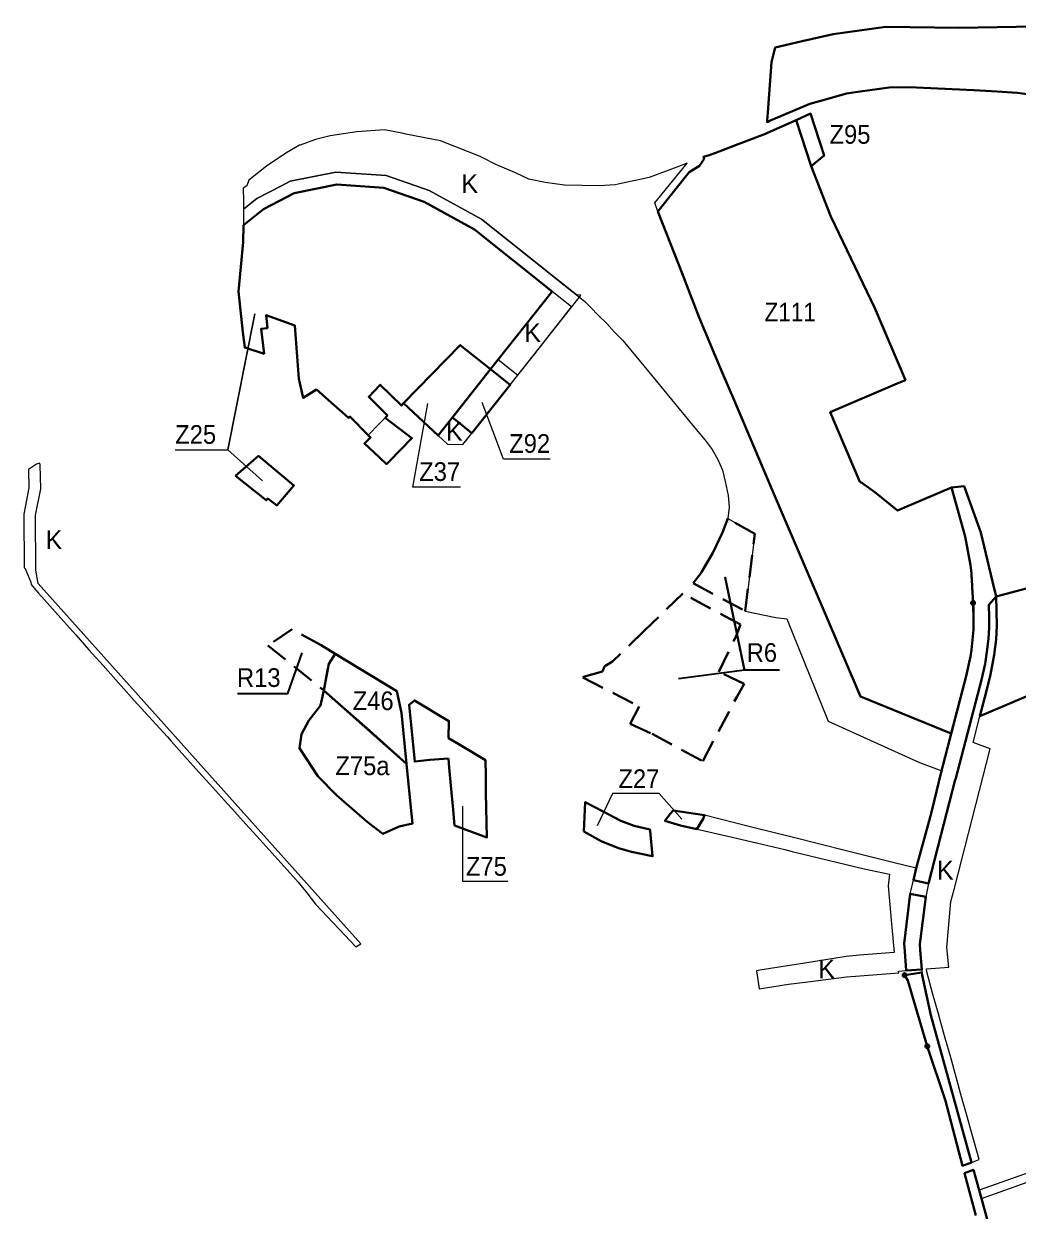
# Model space of a CAD drawing. Extents: x -650276 to -642489, y -1074311 to -1066658.
# Drawn here: x -650276 to -649001, y -1070690 to -1069167 of the extents above; entities that cross this region are included whole.
import ezdxf

# ---------------------------------------------------------------- set-up
doc = ezdxf.new("R2010")
doc.units = 0
doc.header["$LTSCALE"] = 9.6
doc.header["$PDMODE"] = 32
doc.header["$PDSIZE"] = 4.8
doc.linetypes.add('MEDIUM_DASHED', pattern=[4.5, 3, -1.5])
for name, color, linetype, lineweight in [('42', 7, 'Continuous', 25), ('44', 7, 'Continuous', 40), ('45', 7, 'Continuous', 40), ('46', 7, 'Continuous', 13), ('47', 7, 'Continuous', 13), ('48', 7, 'Continuous', 13), ('61', 7, 'MEDIUM_DASHED', 40), ('62', 7, 'Continuous', 35)]:
    doc.layers.add(name, color=color, linetype=linetype, lineweight=lineweight)

msp = doc.modelspace()

# ---------------------------------------------------------------- linework, layer by layer
at = {"layer": '42'}
msp.add_lwpolyline([(-649641.978, -1069618.226), (-649572.972, -1069530.758), (-649561.91, -1069516.78), (-649561.17, -1069515.83), (-649566.951, -1069515.099), (-649688.625, -1069418.156), (-649755.971, -1069381.179), (-649810.846, -1069362.154), (-649875.434, -1069357.751), (-649934.363, -1069369.537), (-649945.397, -1069375.277), (-649977.239, -1069391.714), (-649994.329, -1069405.451), (-649994.293, -1069425.949), (-649994.53, -1069447.61), (-650000.59, -1069511.15), (-649992.59, -1069582.88), (-649967.81, -1069590.74), (-649971.38, -1069558.79), (-649963.43, -1069557.91), (-649965.26, -1069541.51), (-649928.48, -1069554.57), (-649924.62, -1069608.53), (-649923.17, -1069623.14), (-649918.35, -1069643.45), (-649917.38, -1069647.56), (-649900.64, -1069636.78), (-649877.82, -1069656.83), (-649859.96, -1069672.53), (-649859.17, -1069673.22), (-649857.49, -1069671.46), (-649833.94, -1069695.24), (-649833.94, -1069695.24), (-649819.98, -1069680.92), (-649809.47, -1069670.13), (-649833.38, -1069646.08), (-649818.71, -1069630.64), (-649791.3, -1069657.21), (-649788.91, -1069654.4), (-649744.517, -1069695.746), (-649744.517, -1069695.746), (-649732.52, -1069706.92), (-649712.64, -1069707.43), (-649708.322, -1069702.293), (-649701.211, -1069692.826), (-649651.773, -1069630.879), (-649651.846, -1069630.821), (-649651.846, -1069630.82)], close=True, dxfattribs=at)
at = {"layer": '44'}
for p, q in [((-649058.858, -1069889.759), (-649057.868, -1069910.51)), ((-649057.134, -1069932.873), (-649057.868, -1069910.51)), ((-649146.163, -1070347.543), (-649145.424, -1070357.637))]:
    msp.add_line(p, q, dxfattribs=at)
for points in [[(-648781.015, -1069167.44), (-649076.02, -1069172.683), (-649169.781, -1069171.432), (-649237.512, -1069180.731), (-649277.021, -1069189.913), (-649306.455, -1069196.754), (-649311.633, -1069197.958), (-649316.47, -1069216.91), (-649321.32, -1069281.47), (-649322.09, -1069291.73), (-649322.22, -1069293.54), (-649319.72, -1069292.47), (-649267.5, -1069270.41), (-649242.5, -1069263.3), (-649220.18, -1069257.03), (-649202.63, -1069254.4), (-649165.62, -1069249.43), (-649139.63, -1069248.73), (-649056.95, -1069252.55), (-649026.955, -1069254.366), (-649001.3, -1069255.92), (-648968.49, -1069260.36)], [(-649061.138, -1069979.243), (-649061.138, -1069979.243), (-649061.139, -1069979.254), (-649066.487, -1070004.267), (-649098.65, -1070127.795), (-649110.925, -1070177.113), (-649114.174, -1070189.816), (-649130.712, -1070250.935), (-649134.294, -1070266.095), (-649115.159, -1070270.568), (-649095.152, -1070193.731), (-649093.095, -1070186.132), (-649095.152, -1070193.731), (-649080.924, -1070137.409), (-649080.38, -1070136.996), (-649047.131, -1070009.304), (-649042.468, -1069988.477), (-649042.468, -1069988.477), (-649039.966, -1069973.035), (-649037.98, -1069956.626), (-649037.322, -1069942.129), (-649037.137, -1069928.996), (-649037.665, -1069912.977), (-649028.017, -1069902.109), (-649032.928, -1069882.782), (-649048, -1069820), (-649069.4, -1069760.67), (-649085.41, -1069762.44), (-649068, -1069825.147), (-649060.897, -1069861.994)], [(-649138.43, -1070283.6), (-649146.163, -1070347.543), (-649146.163, -1070347.543)], [(-649125.503, -1070355.837), (-649126.069, -1070348.097), (-649118.257, -1070287.455), (-649138.43, -1070283.6)], [(-649145.424, -1070357.637), (-649143.633, -1070382.123), (-649123.693, -1070380.572), (-649125.503, -1070355.837)], [(-649059.951, -1070628.223), (-649112.14, -1070439.152), (-649123.138, -1070388.16), (-649123.385, -1070384.775), (-649145.73, -1070387.91)], [(-649145.73, -1070387.91), (-649141.48, -1070394.84), (-649132.07, -1070426.81), (-649116.56, -1070479.19)], [(-649116.56, -1070479.19), (-649093.2, -1070549.1), (-649071.33, -1070632.6), (-649059.951, -1070628.223)], [(-649025.129, -1070754.377), (-649047.11, -1070674.743), (-649050.081, -1070663.981), (-649057.338, -1070637.689), (-649068.65, -1070642.23), (-649068.65, -1070642.23), (-649054.31, -1070696.44)]]:
    msp.add_lwpolyline(points, dxfattribs=at)
msp.add_lwpolyline([(-649701.211, -1069692.826), (-649651.773, -1069630.879), (-649677.124, -1069610.681), (-649726.033, -1069672.415)], close=True, dxfattribs=at)
at = {"layer": '44', "lineweight": 13}
msp.add_lwpolyline([(-649600.782, -1069725.864), (-649660.57, -1069725.864), (-649688.04, -1069653.176)], dxfattribs=at)
at = {"layer": '44'}
for centre, radius, start, end in [((-649633.43, -1069918.001), 575.266, 2.81398, 5.58706), ((-649347.129, -1069931.193), 290, 350.46253, 4.08974), ((-649347.129, -1069931.193), 290, 359.66809, 4.08974)]:
    msp.add_arc(centre, radius, start, end, dxfattribs=at)
for p in [(-649145.73, -1070387.91), (-649116.56, -1070479.19)]:
    msp.add_point(p, dxfattribs=at)
at = {"layer": '45'}
msp.add_line((-649057.868, -1069910.51), (-649058.82, -1069890.548), dxfattribs=at)
for points in [[(-649060.897, -1069861.994), (-649068, -1069825.147), (-649085.41, -1069762.44), (-649085.41, -1069762.44), (-649099.75, -1069768.575), (-649154.76, -1069792.11), (-649184.05, -1069768.45), (-649200.64, -1069756.53), (-649202.99, -1069754.99), (-649241.11, -1069665.9), (-649155.082, -1069629.097), (-649144.57, -1069624.6), (-649184.1, -1069532.2), (-649240.202, -1069414.528), (-649244.08, -1069404.753), (-649265.774, -1069350.068), (-649284.695, -1069291.033), (-649321.69, -1069307.61), (-649324.3, -1069308.59), (-649359.48, -1069321.82), (-649389.4, -1069333.35), (-649396.52, -1069336.09), (-649403.92, -1069338.26), (-649403.03, -1069340.66), (-649408.81, -1069349.89), (-649422.19, -1069357.99), (-649462.25, -1069408.32), (-649435.578, -1069476.772), (-649435.578, -1069476.772), (-649431.761, -1069486.57), (-649416.52, -1069525.68), (-649409.355, -1069544.517), (-649388.438, -1069594.296), (-649379.32, -1069615.71), (-649364.44, -1069650.55), (-649312.03, -1069773.33), (-649246.81, -1069926.27), (-649246.81, -1069926.27), (-649239.635, -1069943.094), (-649202.375, -1070030.469), (-649202.375, -1070030.469), (-649085.737, -1070078.201), (-649066.487, -1070004.267), (-649061.139, -1069979.254), (-649061.138, -1069979.243), (-649061.138, -1069979.243)], [(-648906.547, -1069869.711), (-649007.37, -1069896.602), (-649028.017, -1069902.109), (-649027.457, -1069939.468), (-649028.007, -1069957.455), (-649030.869, -1069977.253), (-649035.775, -1070004.354), (-649042.536, -1070031.342), (-649048.918, -1070055.852), (-648978.654, -1070025.669)], [(-649730.837, -1070084.028), (-649730.6, -1070061.98), (-649774.73, -1070035.58), (-649781.53, -1070041.2), (-649774.45, -1070113.92), (-649754.82, -1070111.89), (-649731.12, -1070109.96)], [(-649730.837, -1070084.028), (-649730.6, -1070061.98), (-649774.73, -1070035.58), (-649781.53, -1070041.2), (-649774.45, -1070113.92), (-649754.82, -1070111.89), (-649731.12, -1070109.96)], [(-649731.12, -1070109.96), (-649730.57, -1070115.76), (-649730, -1070122.01), (-649726.22, -1070162.75), (-649725.49, -1070170.64), (-649723.17, -1070195.81), (-649682.04, -1070211.58), (-649683.12, -1070154.14), (-649682.98, -1070132.1), (-649683.57, -1070112.05), (-649717.72, -1070091.61), (-649730.837, -1070084.028)], [(-649731.12, -1070109.96), (-649730.57, -1070115.76), (-649730, -1070122.01), (-649726.22, -1070162.75), (-649725.49, -1070170.64), (-649723.17, -1070195.81), (-649682.04, -1070211.58), (-649683.12, -1070154.14), (-649682.98, -1070132.1), (-649683.57, -1070112.05), (-649717.72, -1070091.61), (-649730.837, -1070084.028)]]:
    msp.add_lwpolyline(points, dxfattribs=at)
for points in [[(-649265.774, -1069350.068), (-649249.069, -1069336.66), (-649266.331, -1069282.804), (-649284.695, -1069291.033)], [(-649994.293, -1069425.949), (-649994.293, -1069425.949), (-649994.53, -1069447.61), (-650000.59, -1069511.15), (-649994.794, -1069563.119), (-649992.59, -1069582.88), (-649967.81, -1069590.74), (-649971.38, -1069558.79), (-649963.43, -1069557.91), (-649965.26, -1069541.51), (-649928.48, -1069554.57), (-649923.17, -1069623.14), (-649917.38, -1069647.56), (-649900.64, -1069636.78), (-649900.64, -1069636.78), (-649877.82, -1069656.83), (-649859.96, -1069672.53), (-649859.17, -1069673.22), (-649857.49, -1069671.46), (-649833.94, -1069695.24), (-649831.087, -1069698.045), (-649838.99, -1069706.15), (-649819.9, -1069723.61), (-649810.41, -1069732.28), (-649807.66, -1069729.46), (-649792.13, -1069713.65), (-649777.94, -1069699.2), (-649812.153, -1069672.884), (-649809.47, -1069670.13), (-649833.38, -1069646.08), (-649818.71, -1069630.64), (-649791.3, -1069657.21), (-649788.91, -1069654.4), (-649715.908, -1069579.804), (-649677.124, -1069610.681), (-649667.188, -1069598.14), (-649598.004, -1069510.814), (-649697.525, -1069431.522), (-649762.488, -1069395.854), (-649814.067, -1069377.972), (-649874.391, -1069373.859), (-649929.015, -1069384.784), (-649968.465, -1069405.189), (-649994.293, -1069425.949), (-649994.293, -1069425.949)], [(-649788.91, -1069654.4), (-649744.517, -1069695.746), (-649677.124, -1069610.681), (-649715.908, -1069579.804)], [(-649788.91, -1069654.4), (-649744.517, -1069695.746), (-649677.124, -1069610.681), (-649715.908, -1069579.804)], [(-650004.59, -1069747.27), (-649974.86, -1069721.96), (-649966.52, -1069728.87), (-649929.38, -1069759.65), (-649951.56, -1069785.42), (-649963, -1069776.7), (-649965, -1069778.7)], [(-650004.59, -1069747.27), (-649974.86, -1069721.96), (-649966.52, -1069728.87), (-649929.38, -1069759.65), (-649951.56, -1069785.42), (-649963, -1069776.7), (-649965, -1069778.7)], [(-649891.21, -1070022.68), (-649832.007, -1070074.751), (-649784.87, -1070116.76), (-649791.31, -1070051.51), (-649797.45, -1070023.77), (-649876.31, -1069975.93), (-649884.59, -1069988.57)], [(-649891.21, -1070022.68), (-649832.007, -1070074.751), (-649784.87, -1070116.76), (-649791.31, -1070051.51), (-649797.45, -1070023.77), (-649876.31, -1069975.93), (-649884.59, -1069988.57)], [(-649891.21, -1070022.68), (-649895.45, -1070042.15), (-649910.34, -1070061.29), (-649919.55, -1070079.01), (-649922.3, -1070096.9), (-649898.55, -1070132.9), (-649874.94, -1070157.19), (-649835.28, -1070191.27), (-649815.33, -1070206.63), (-649794.37, -1070197.2), (-649777.29, -1070193.57), (-649779.75, -1070168.69), (-649784.87, -1070116.76)], [(-649557.21, -1070203.53), (-649555.44, -1070165.91), (-649532.57, -1070178.08), (-649509.72, -1070190.24), (-649492.67, -1070196.34), (-649472.6, -1070201.15), (-649472.43, -1070202.9), (-649469.176, -1070235.365), (-649496, -1070230), (-649513, -1070225), (-649535, -1070216)], [(-649557.21, -1070203.53), (-649555.44, -1070165.91), (-649532.57, -1070178.08), (-649509.72, -1070190.24), (-649492.67, -1070196.34), (-649472.6, -1070201.15), (-649472.43, -1070202.9), (-649469.176, -1070235.365), (-649496, -1070230), (-649513, -1070225), (-649535, -1070216)], [(-649442.63, -1070176.69), (-649402.29, -1070182.92), (-649404.2, -1070187.43), (-649412.2, -1070200.71), (-649433.3, -1070195.89), (-649453.27, -1070190.02), (-649446.19, -1070180.76)], [(-649442.63, -1070176.69), (-649402.29, -1070182.92), (-649404.2, -1070187.43), (-649412.2, -1070200.71), (-649433.3, -1070195.89), (-649453.27, -1070190.02), (-649446.19, -1070180.76)]]:
    msp.add_lwpolyline(points, close=True, dxfattribs=at)
for centre, radius, start, end in [((-649649.71, -1069919.176), 591.583, 2.77379, 5.54687), ((-649347.129, -1069931.193), 290, 350.46253, 4.08974)]:
    msp.add_arc(centre, radius, start, end, dxfattribs=at)
msp.add_point((-649057.868, -1069910.51), dxfattribs=at)
at = {"layer": '46'}
for points in [[(-650082.06, -1069714.05), (-650014.296, -1069714.05), (-649979.397, -1069539.747), (-650014.296, -1069714.05), (-649969.577, -1069753.88)], [(-649715.535, -1069761.925), (-649776.818, -1069761.925), (-649757.387, -1069654.603)], [(-649715.535, -1069761.925), (-649776.818, -1069761.925), (-649757.387, -1069654.603)], [(-650082.06, -1069714.05), (-650014.296, -1069714.05), (-650014.296, -1069714.05), (-649969.577, -1069753.88)], [(-649431.69, -1070187.9), (-649460.604, -1070155.007), (-649520.489, -1070155.007), (-649540.207, -1070196.319)], [(-649654.738, -1070267.746), (-649712.819, -1070267.746), (-649712.819, -1070267.746), (-649712.586, -1070171.248)]]:
    msp.add_lwpolyline(points, dxfattribs=at)
at = {"layer": '47'}
msp.add_line((-649115.159, -1070270.568), (-649118.257, -1070287.455), dxfattribs=at)
for points in [[(-649509.42, -1069372.61), (-649517.17, -1069374.3), (-649537.32, -1069375.23), (-649582.25, -1069374.51), (-649607.18, -1069370.92), (-649627.76, -1069366.8), (-649645.03, -1069358.8), (-649670.23, -1069347.9), (-649688.73, -1069338.7), (-649690.59, -1069337.98), (-649741.5, -1069317.74), (-649785.8, -1069308.94), (-649789, -1069308.31), (-649813.3, -1069303.66), (-649848.62, -1069305.95), (-649882.93, -1069311.1), (-649901.58, -1069316.01), (-649921.54, -1069323.03), (-649922.11, -1069323.35), (-649939.81, -1069333.47), (-649964.53, -1069350.02), (-649987.12, -1069368.03), (-649989.67, -1069375.36), (-649994.38, -1069378.33), (-649994.35, -1069394.43), (-649994.34, -1069398.8), (-649994.329, -1069405.451), (-649977.239, -1069391.714), (-649945.397, -1069375.277), (-649934.363, -1069369.537), (-649875.434, -1069357.751), (-649810.846, -1069362.154), (-649755.971, -1069381.179), (-649688.625, -1069418.156), (-649582.972, -1069502.334)], [(-649424.8, -1069346.14), (-649438.17, -1069351.27), (-649473.35, -1069364.76), (-649473.35, -1069364.76), (-649509.42, -1069372.61)], [(-649431.761, -1069486.57), (-649435.578, -1069476.772), (-649435.578, -1069476.772), (-649462.25, -1069408.32), (-649466.045, -1069397.373), (-649424.8, -1069346.14)], [(-649409.349, -1069544.532), (-649409.355, -1069544.517), (-649416.52, -1069525.68), (-649431.761, -1069486.57)], [(-649582.972, -1069502.334), (-649566.951, -1069515.099), (-649566.951, -1069515.099)], [(-649572.987, -1069530.746), (-649598.004, -1069510.814), (-649667.188, -1069598.14), (-649641.978, -1069618.226)], [(-649566.951, -1069515.099), (-649556.25, -1069523.62), (-649548.881, -1069530.963), (-649538.49, -1069541.54)], [(-649641.978, -1069618.226), (-649620.45, -1069590.75), (-649572.987, -1069530.746)], [(-649538.49, -1069541.54), (-649527.84, -1069552.16), (-649517.81, -1069563.27), (-649507.23, -1069573.85), (-649474.46, -1069613.59), (-649415.12, -1069685.26), (-649401.77, -1069701.47), (-649392.85, -1069713.53), (-649385.25, -1069726.48), (-649379.49, -1069740.04), (-649376.01, -1069754.58), (-649372.2, -1069772.58), (-649370.94, -1069787.45), (-649372.56, -1069802.33), (-649372.56, -1069802.33), (-649338, -1069822), (-649350.222, -1069920.873), (-649310.738, -1069929.342), (-649296.851, -1069931.092)], [(-649379.32, -1069615.71), (-649407.002, -1069550.701), (-649409.349, -1069544.532)], [(-649202.375, -1070030.469), (-649239.635, -1069943.094), (-649246.81, -1069926.27), (-649246.81, -1069926.27), (-649312.03, -1069773.33), (-649364.44, -1069650.55), (-649379.32, -1069615.71)], [(-649701.218, -1069692.82), (-649726.033, -1069672.415), (-649744.517, -1069695.746), (-649732.52, -1069706.92), (-649712.64, -1069707.43)], [(-649712.64, -1069707.43), (-649712.64, -1069707.43), (-649701.218, -1069692.82)], [(-650260.665, -1069868.303), (-650260.748, -1069867.327), (-650261.204, -1069797.969), (-650254.411, -1069764.006), (-650255.21, -1069733.253), (-650255.716, -1069731.162), (-650259.97, -1069732.29), (-650264.91, -1069735.69), (-650270.059, -1069739.232)], [(-650270.059, -1069739.232), (-650269.449, -1069762.714), (-650276.214, -1069796.532), (-650275.76, -1069865.474), (-650274.95, -1069865.62)], [(-650274.95, -1069865.62), (-650273.61, -1069868.62), (-650266.89, -1069883.7)], [(-650266.89, -1069883.7), (-650266.68, -1069886.78), (-650262.64, -1069891.57), (-650257.16, -1069898.07), (-650224.71, -1069934.41), (-650209.51, -1069951.43), (-650192.51, -1069970.47), (-650174.3, -1069990.86), (-650157.87, -1070009.26), (-650151.03, -1070016.84), (-650134.26, -1070035.45), (-650106.76, -1070065.96), (-650091.89, -1070082.46), (-650087.18, -1070087.68), (-650076.72, -1070099.29), (-650051.33, -1070127.45), (-650037.78, -1070142.48), (-650018.41, -1070163.97), (-650005.3, -1070178.51), (-649990.95, -1070194.43), (-649977.05, -1070209.85), (-649946.39, -1070243.87), (-649930.46, -1070261.54), (-649924.15, -1070268.55), (-649913.03, -1070282.44), (-649901.59, -1070296.73), (-649871.28, -1070329.01), (-649850.04, -1070351.64), (-649843.513, -1070347.685), (-650257.713, -1069885.547), (-650260.665, -1069868.303)], [(-649057.722, -1070089.665), (-649048.918, -1070055.852), (-649037.411, -1070011.659), (-649032.972, -1069991.835), (-649028.007, -1069957.455), (-649027.566, -1069943.013), (-649027.135, -1069928.902), (-649027.569, -1069915.721), (-649028.017, -1069902.109), (-649037.665, -1069912.977), (-649037.137, -1069928.996), (-649037.199, -1069933.38), (-649037.322, -1069942.129), (-649037.98, -1069956.626), (-649039.623, -1069970.202), (-649042.468, -1069988.477), (-649047.131, -1070009.304), (-649055.689, -1070042.169), (-649061.354, -1070063.169), (-649067.061, -1070085.844), (-649079.268, -1070132.727), (-649080.38, -1070136.996), (-649080.872, -1070137.37), (-649083.089, -1070145.979)], [(-649296.851, -1069931.092), (-649289.95, -1069948.146), (-649243.846, -1070062.071), (-649126.437, -1070115.217), (-649126.437, -1070115.217), (-649098.101, -1070125.688), (-649085.737, -1070078.201), (-649202.375, -1070030.469)], [(-649089.07, -1070377.88), (-649091.46, -1070352.73), (-649086.157, -1070293.589), (-649082.233, -1070278.265), (-649036.031, -1070097.854), (-649057.722, -1070089.665)], [(-649083.089, -1070145.979), (-649095.152, -1070193.731), (-649093.095, -1070186.132), (-649095.152, -1070193.731), (-649111.303, -1070255.758), (-649095.152, -1070193.731), (-649115.159, -1070270.568)], [(-649118.257, -1070287.455), (-649126.069, -1070348.097), (-649125.503, -1070355.837), (-649123.693, -1070380.572)], [(-649123.693, -1070380.572), (-649123.385, -1070384.775), (-649123.138, -1070388.16), (-649112.14, -1070439.152), (-649059.951, -1070628.223), (-649049.96, -1070624.38), (-649055.93, -1070603.08), (-649058.38, -1070594.33), (-649065.42, -1070569.21), (-649072.47, -1070544.09), (-649079.51, -1070518.97), (-649086.55, -1070493.85), (-649093.59, -1070468.73), (-649100.01, -1070445.82), (-649102.31, -1070437.61), (-649109.76, -1070411.05), (-649117.36, -1070383.93), (-649117.374, -1070380.081), (-649089.07, -1070377.88)]]:
    msp.add_lwpolyline(points, dxfattribs=at)
for points in [[(-649159.19, -1070358.82), (-649197.91, -1070361.8), (-649203.4, -1070362.23), (-649220.47, -1070363.94), (-649231.39, -1070365.69), (-649273.57, -1070372.44), (-649304.18, -1070377.35), (-649331.3, -1070381.69), (-649335.79, -1070382.41), (-649332.2, -1070405.42), (-649294.79, -1070399.65), (-649269.769, -1070396.502), (-649220.16, -1070390.26), (-649202.969, -1070388.965), (-649153.11, -1070385.21), (-649153.64, -1070382.9), (-649143.633, -1070382.123), (-649146.163, -1070347.543), (-649138.43, -1070283.6), (-649134.294, -1070266.095), (-649130.712, -1070250.935), (-649160.748, -1070243.413), (-649220.52, -1070228.443), (-649288.379, -1070211.449), (-649310.998, -1070205.784), (-649342.149, -1070197.982), (-649402.29, -1070182.92), (-649404.2, -1070187.43), (-649412.2, -1070200.71), (-649408.24, -1070201.62), (-649391.184, -1070205.516), (-649372.69, -1070209.74), (-649335.914, -1070218.359), (-649299.227, -1070226.958), (-649289.83, -1070229.16), (-649197.55, -1070251.65), (-649164.91, -1070258.55), (-649166.86, -1070273.48), (-649162.91, -1070317.47)], [(-649014.888, -1070782.994), (-648966.35, -1070764.7), (-648908.94, -1070740.19), (-648892.215, -1070733.293), (-648927.2, -1070637.98), (-648941.064, -1070599.735), (-648965.569, -1070610.382), (-648956.687, -1070630.825), (-649050.081, -1070663.981), (-649047.11, -1070674.743), (-648952.455, -1070640.564), (-648922.196, -1070710.207), (-648924.668, -1070712.022), (-648943.837, -1070720.104), (-649025.129, -1070754.377)]]:
    msp.add_lwpolyline(points, close=True, dxfattribs=at)
at = {"layer": '61'}
for points in [[(-649372.56, -1069802.33), (-649379.19, -1069820.24), (-649391.86, -1069846.18), (-649406.53, -1069871.59), (-649417.234, -1069885.193), (-649350.222, -1069920.873), (-649338, -1069822)], [(-649430.515, -1069898.514), (-649479.08, -1069945.53), (-649520.6, -1069985.72), (-649530.31, -1069991.5), (-649530.99, -1069991.9), (-649533.61, -1069998.6), (-649557.92, -1070005.19), (-649558.56, -1070006.13), (-649486.5, -1070043.26), (-649497.95, -1070065.49), (-649469.85, -1070078.3), (-649404.76, -1070113.41), (-649360.74, -1070030.35), (-649351.66, -1070014.26), (-649384.249, -1069998.959), (-649361.46, -1069951.93), (-649356.458, -1069937.945)], [(-649931.76, -1069944.31), (-649962.859, -1069964.896), (-649891.21, -1070022.68), (-649884.59, -1069988.57), (-649876.31, -1069975.93), (-649894.68, -1069964.78)]]:
    msp.add_lwpolyline(points, close=True, dxfattribs=at)
at = {"layer": '62'}
for points in [[(-649306.343, -1069996.537), (-649351.328, -1069996.537), (-649375.864, -1069878.046), (-649351.328, -1069996.537), (-649435.663, -1070007.798)], [(-650001.823, -1070026.616), (-649937.373, -1070026.616), (-649918.861, -1069974.471)]]:
    msp.add_lwpolyline(points, dxfattribs=at)
at = {"layer": '62', "lineweight": 13}
msp.add_lwpolyline([(-650001.823, -1070026.616), (-649937.373, -1070026.616), (-649918.861, -1069974.471)], dxfattribs=at)

# ---------------------------------------------------------------- texts
at = {"layer": '44', "width": 0.95}
for s, p in [('Z95', (-649242.024, -1069321.399)), ('Z92', (-649653.123, -1069717.932))]:
    msp.add_text(s, height=24, dxfattribs=at).set_placement(p)
at = {"layer": '46'}
for s, width, p in [('Z111', 0.9, (-649325.444, -1069549.35)), ('Z111', 0.9, (-649325.444, -1069549.35)), ('Z25', 0.95, (-650081.8, -1069706.363)), ('Z37', 0.95, (-649768.624, -1069753.993)), ('Z37', 0.95, (-649768.624, -1069753.993)), ('Z46', 0.95, (-649853.994, -1070048.002)), ('Z46', 0.95, (-649853.994, -1070048.002)), ('Z75a', 0.95, (-649876.242, -1070131.383)), ('Z27', 0.95, (-649512.965, -1070148.029)), ('Z75', 0.95, (-649708.673, -1070260.465))]:
    msp.add_text(s, height=24, dxfattribs=dict(at, width=width)).set_placement(p)
at = {"layer": '48'}
for p in [(-649714.485, -1069384.456), (-649714.485, -1069384.456), (-649633.851, -1069575.59), (-649734.395, -1069702.217), (-650248.205, -1069841.413), (-650248.205, -1069841.413), (-649104.211, -1070265.34), (-649256.486, -1070392.051)]:
    msp.add_text('K', height=24, dxfattribs=at).set_placement(p)
at = {"layer": '62', "width": 0.95}
for s, p in [('R6', (-649348.349, -1069986.108)), ('R13', (-650002.521, -1070018.261)), ('R13', (-650002.521, -1070018.261))]:
    msp.add_text(s, height=24, dxfattribs=at).set_placement(p)

doc.saveas('drawing.dxf')
